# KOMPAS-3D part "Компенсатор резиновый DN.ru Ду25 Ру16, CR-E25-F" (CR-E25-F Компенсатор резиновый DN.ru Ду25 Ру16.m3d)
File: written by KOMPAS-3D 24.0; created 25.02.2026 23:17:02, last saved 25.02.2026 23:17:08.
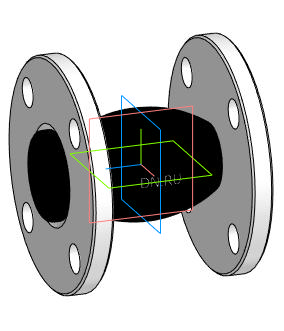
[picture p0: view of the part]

Document properties: Автор: DN.RU; Полное имя файла: D:\PROJECT CAD\DN.RU\...178(4)(ACTUALE). CR-E25-F Компенсатор резиновый DN.ru Ру10-16\DN25_PN16\CR-E25-F Компенсатор резиновый DN.ru Ду25 Ру16.m3d

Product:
- Body: Твердое тело2  | qty 1
    Масса: 1.965785
- Part/product: Компенсатор резиновый DN.ru Ду25 Ру16  | designation CR-E25-F
    Масса: 2.5
    Раздел спецификации: Прочие изделия
    Комментарий: D140-02170
    Примечание: D140-02170
    additional columns: Типовые

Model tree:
1. Твердое тело2  (labels: Твердое тело2)

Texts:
  CR-E25-F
